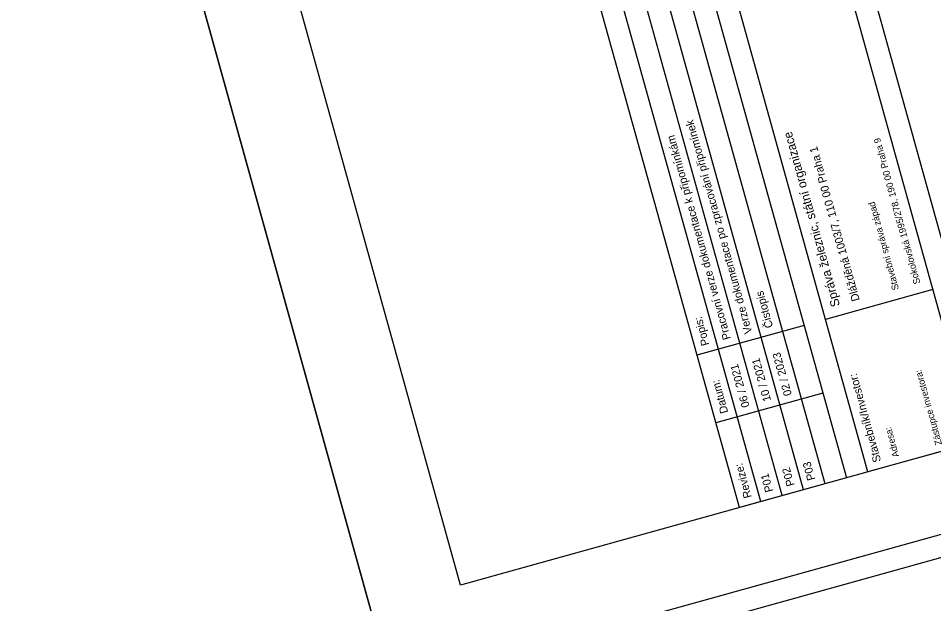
# Model space of a CAD drawing. Extents: x -821172 to -820632, y -1070921 to -1069931.
# Drawn here: x -821042.4 to -820939.6, y -1070062.1 to -1069996.3 of the extents above; entities that cross this region are included whole.
import ezdxf

# ---------------------------------------------------------------- set-up
doc = ezdxf.new("R2010")
doc.units = 0
doc.layers.add('Popisove_pole', color=7, linetype='Continuous')
doc.layers.add('Ram', color=7, linetype='Continuous')

msp = doc.modelspace()

# ---------------------------------------------------------------- linework, layer by layer
at = {"layer": 'Popisove_pole'}
for p, q in [((-820954.19, -1070049.3), (-820976.94, -1069967.41)), ((-820951.78, -1070048.63), (-820974.54, -1069966.74)), ((-820959, -1070050.64), (-820981.76, -1069968.74)), ((-820956.6, -1070049.97), (-820979.35, -1069968.08)), ((-820939.68, -1070026.82), (-820951.72, -1070030.17)), ((-820954.13, -1070030.84), (-820966.17, -1070034.18)), ((-820952.01, -1070038.45), (-820964.06, -1070041.8))]:
    msp.add_line(p, q, dxfattribs=at)
for points in [[(-820992.73, -1070060.01), (-821015.48, -1069978.12), (-820890.23, -1069943.31), (-820867.47, -1070025.21)], [(-820932.51, -1070043.28), (-820955.27, -1069961.38), (-820931.18, -1069954.69), (-820908.42, -1070036.59)], [(-820946.96, -1070047.3), (-820969.72, -1069965.4), (-820957.67, -1069962.05), (-820934.92, -1070043.95)], [(-820961.41, -1070051.31), (-820984.17, -1069969.41), (-820972.13, -1069966.07), (-820949.37, -1070047.96)]]:
    msp.add_lwpolyline(points, close=True, dxfattribs=at)
at = {"layer": 'Ram'}
msp.add_line((-820859.09, -1070034.8), (-821140.43, -1070112.97), dxfattribs=at)
for points in [[(-821000.43, -1070071.48), (-821028.54, -1069970.31), (-820885.46, -1069930.55), (-820857.35, -1070031.72)], [(-821028.54, -1069970.31), (-821000.43, -1070071.48)], [(-820857.35, -1070031.72), (-821000.43, -1070071.48)]]:
    msp.add_lwpolyline(points, dxfattribs=at)

# ---------------------------------------------------------------- texts
at = {"layer": 'Popisove_pole'}
for s, height, p in [('Verze dokumentace po zpracování připomínek', 0.9, (-820959.95, -1070031.65)), ('Pracovní verze dokumentace k připomínkám', 0.9, (-820962.36, -1070032.32)), ('Správa železnic, státní organizace', 1, (-820950.09, -1070028.6)), ('Sokolovská 1995/278, 190 00 Praha 9', 0.75, (-820941.06, -1070026.09)), ('Dlážděná 1003/7, 110 00 Praha 1', 0.9, (-820947.87, -1070027.99)), ('Stavební správa západ', 0.75, (-820943.47, -1070026.76)), ('Čistopis', 0.9, (-820957.61, -1070031)), ('Popis:', 0.9, (-820964.77, -1070032.99)), ('10 / 2021', 0.9, (-820957.83, -1070039.26)), ('02 / 2023', 0.9, (-820955.5, -1070038.62)), ('06 / 2021', 0.9, (-820960.24, -1070039.93)), ('Stavebník/Investor:', 0.9, (-820945.47, -1070046.08)), ('Zástupce investora:', 0.75, (-820938.63, -1070044.18)), ('Datum:', 0.9, (-820962.65, -1070040.6)), ('Adresa:', 0.75, (-820943.45, -1070045.52)), ('Revize:', 0.9, (-820960.01, -1070050.12)), ('P02', 0.9, (-820955.19, -1070048.78)), ('P03', 0.9, (-820952.87, -1070048.13)), ('P01', 0.9, (-820957.6, -1070049.45))]:
    msp.add_text(s, height=height, rotation=105.5289, dxfattribs=at).set_placement(p)

doc.saveas('drawing.dxf')
